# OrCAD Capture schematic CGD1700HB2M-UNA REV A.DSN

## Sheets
1 Power Supplies: size A; title: Power Supplies; rev: V1; note: CGD1700HB2M-UNA
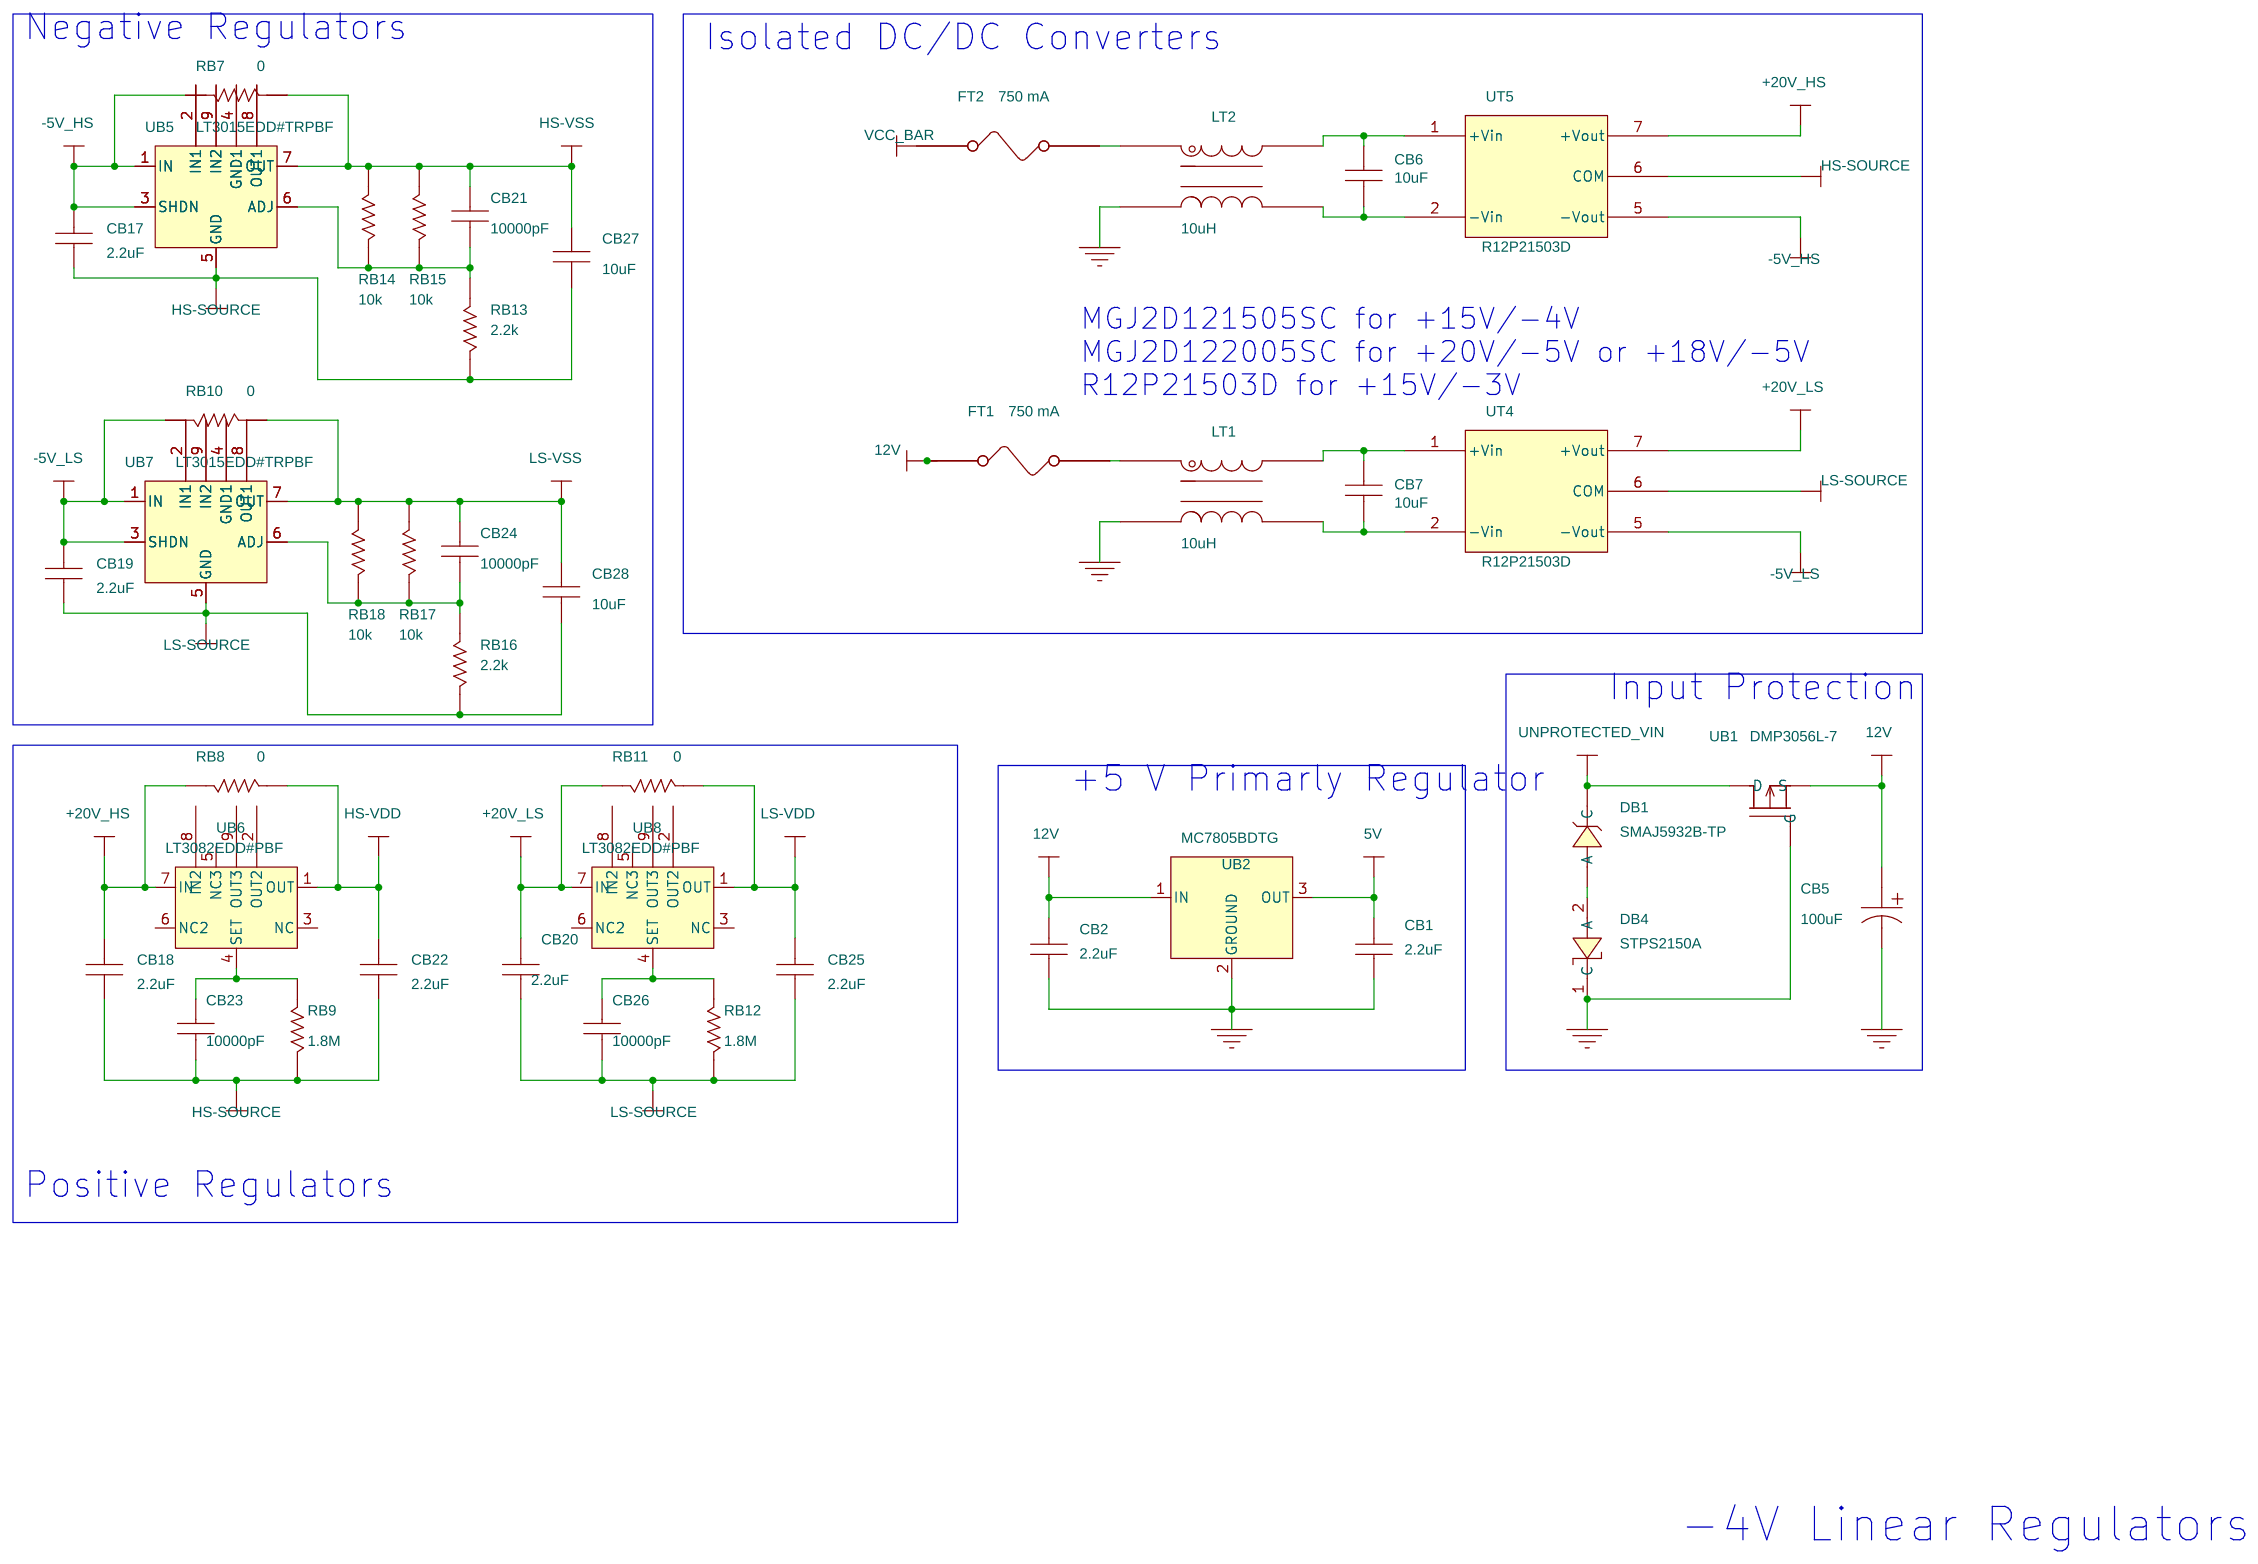
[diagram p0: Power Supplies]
2 Gate Driver: size B; title: Gate Drivers
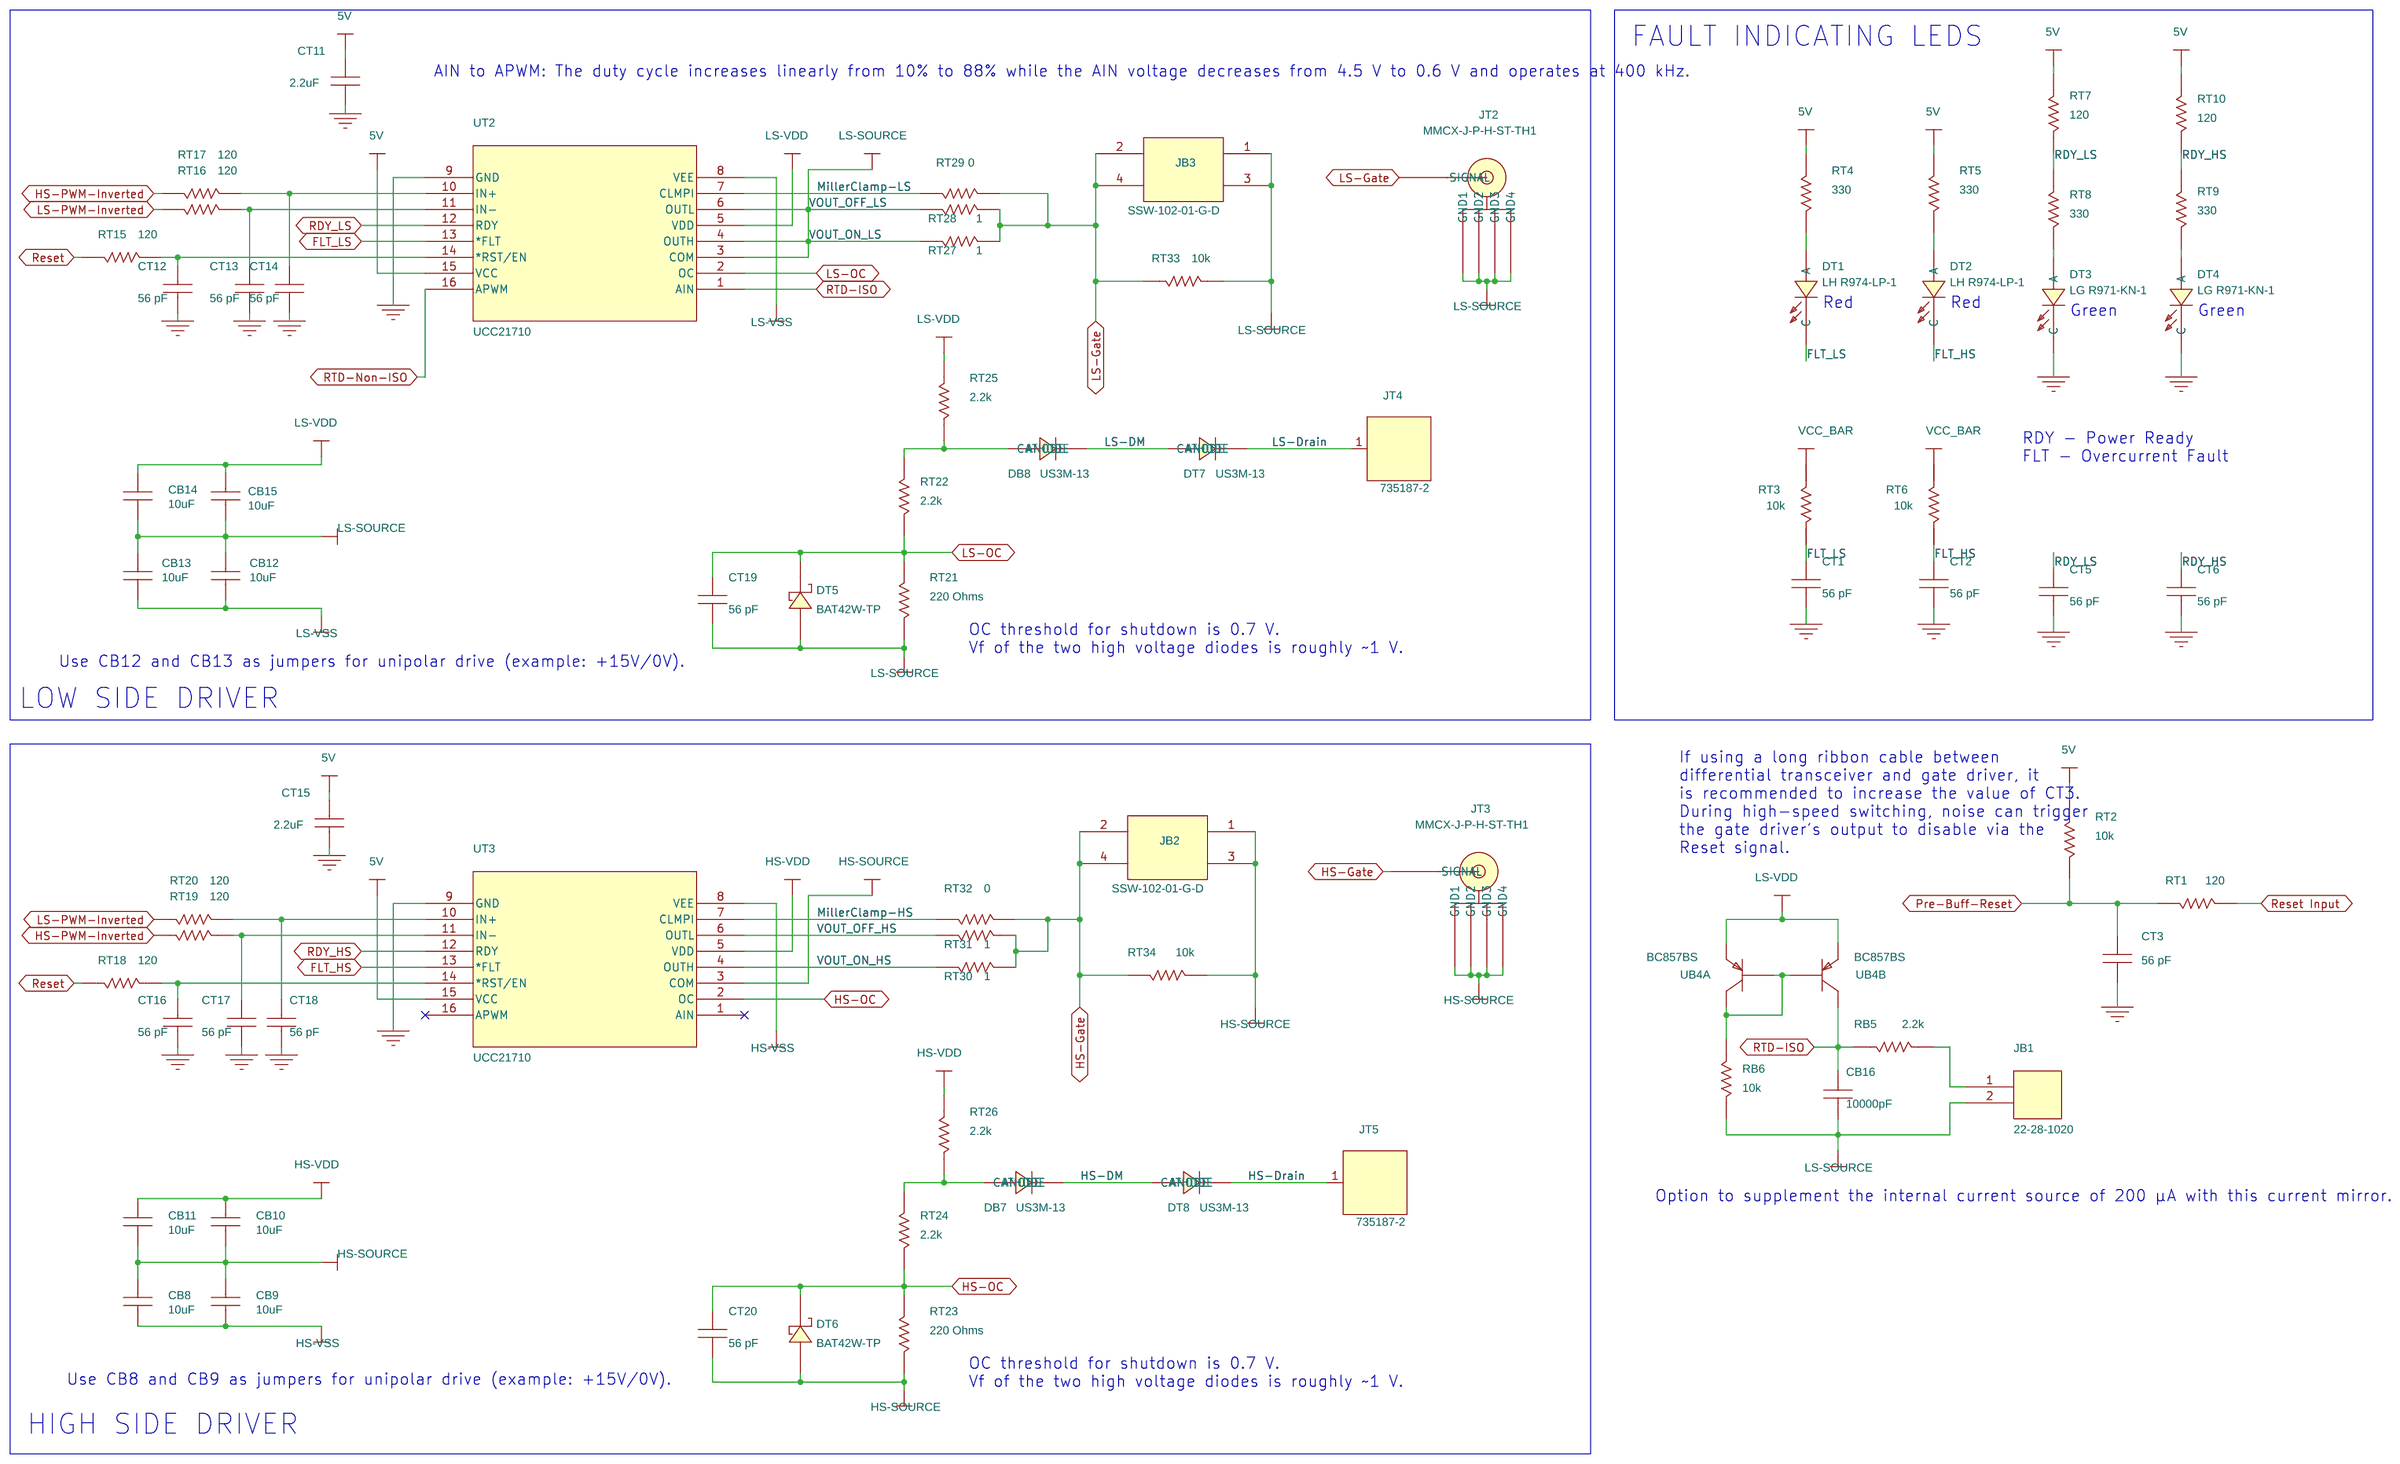
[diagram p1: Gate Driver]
3 Differential Signaling: size B; title: I/O and Conditioning
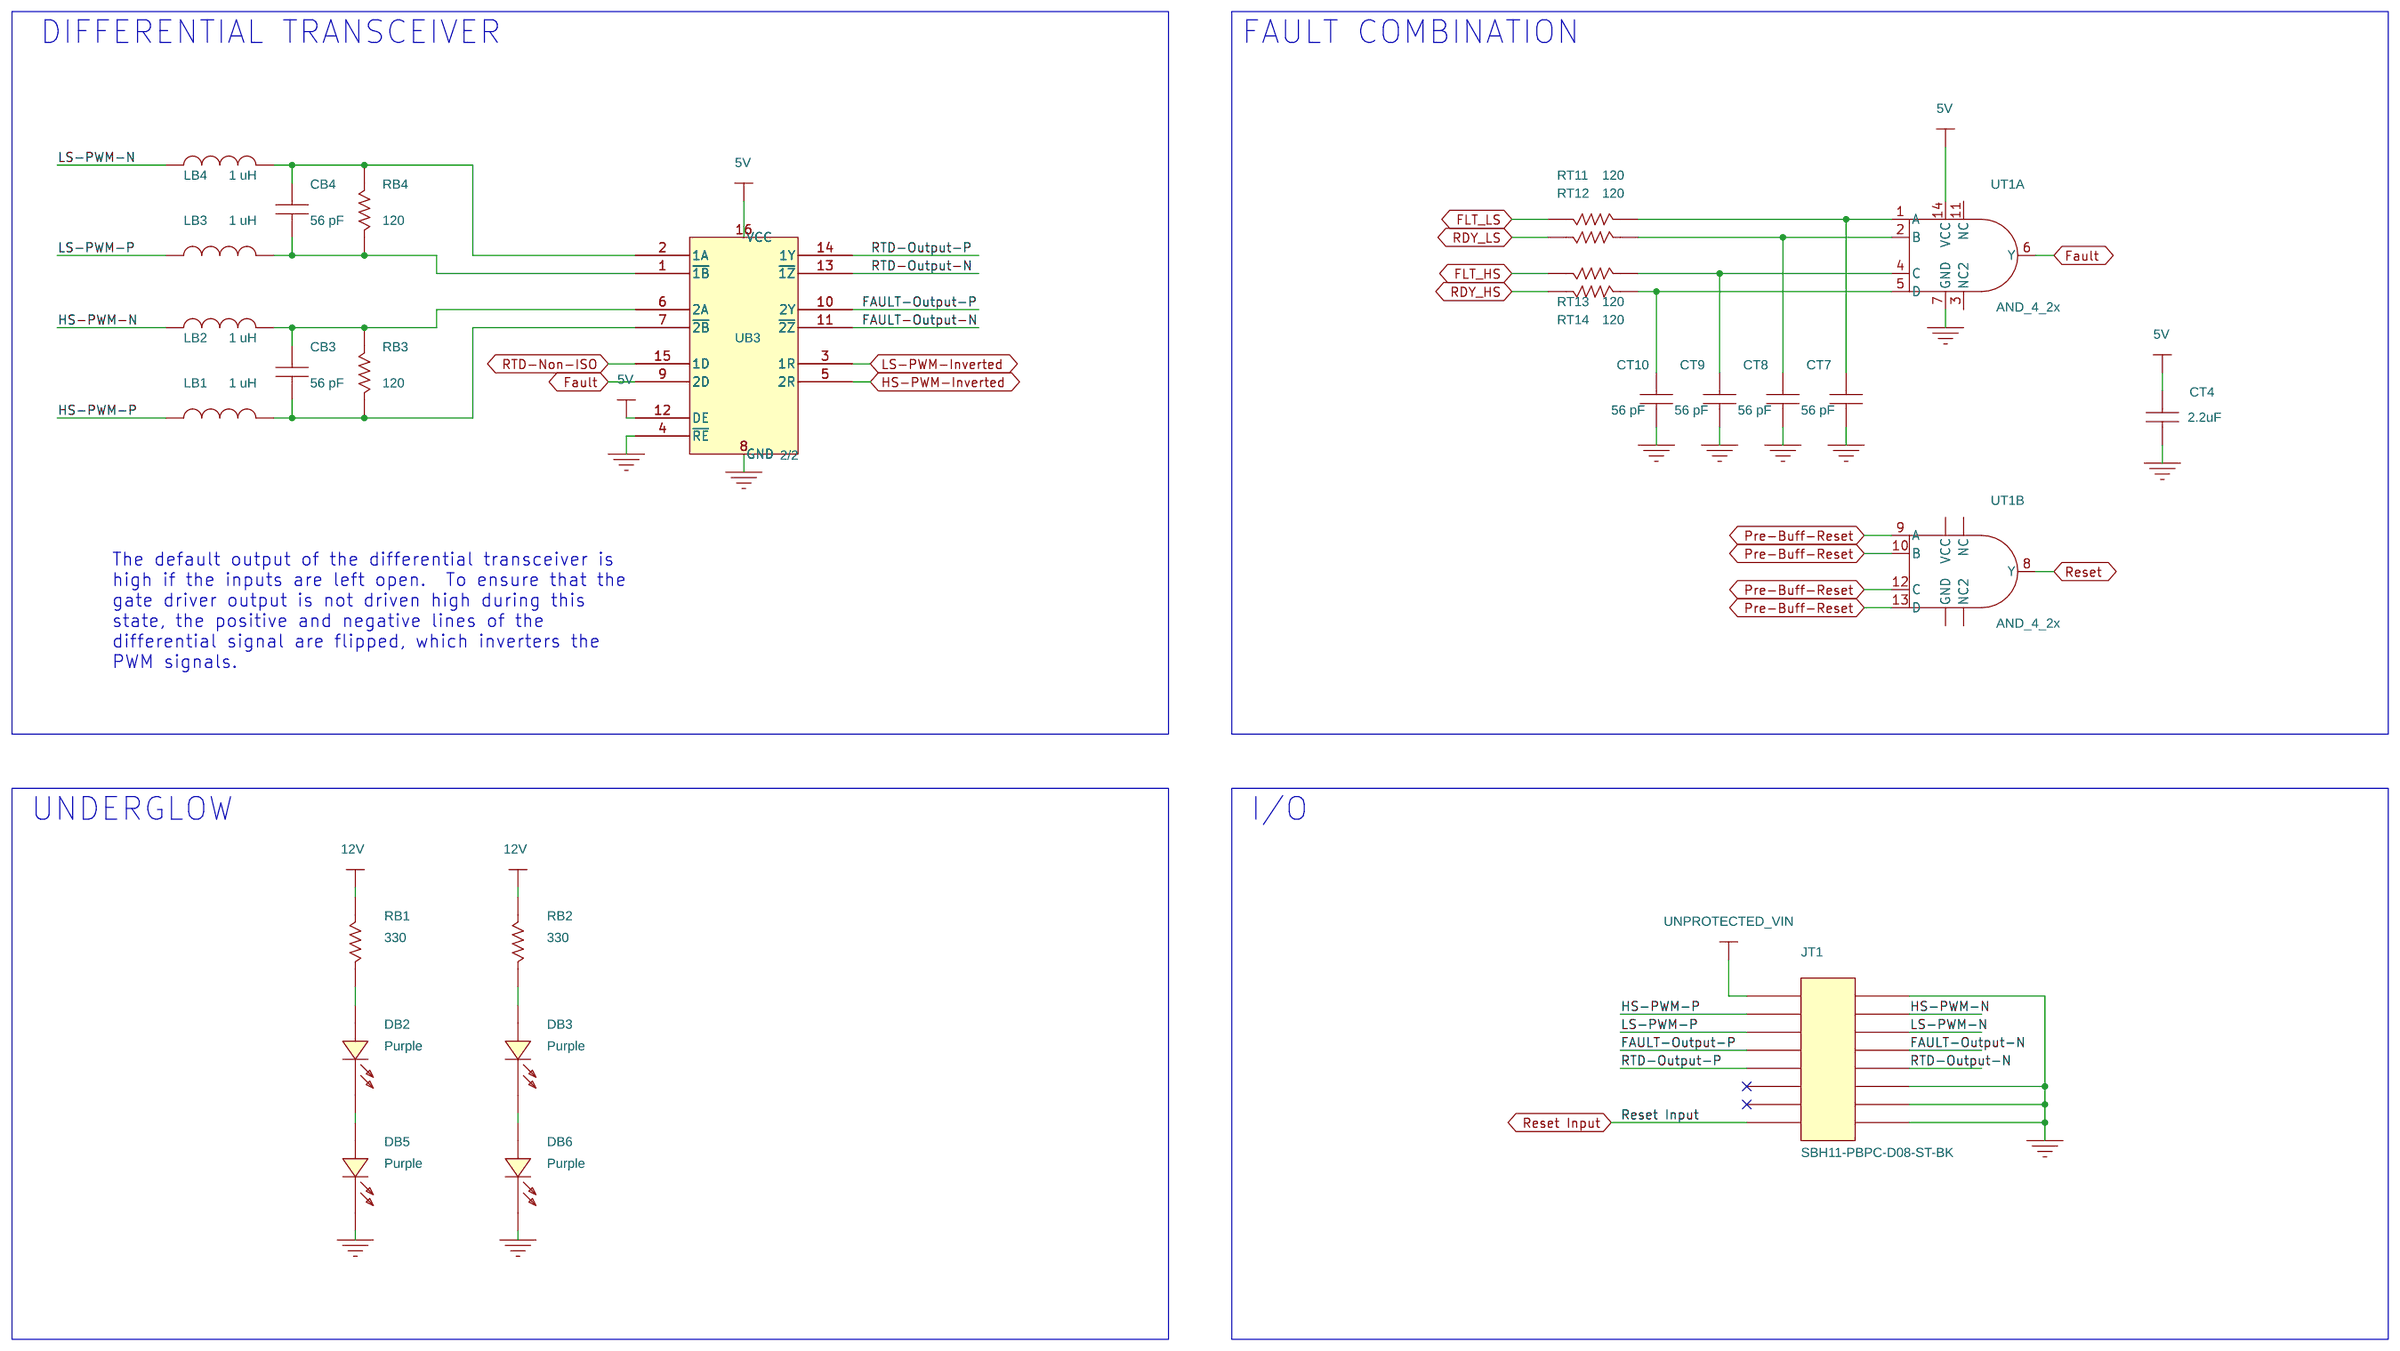
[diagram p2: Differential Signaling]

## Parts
sheet Differential Signaling
CB3  56 pF  [CAPC1608X90N]
CB4  56 pF  [CAPC1608X90N]
CT4  2.2uF  [CAPC1608X90N]
CT7  56 pF  [CAPC1608X90N]
CT8  56 pF  [CAPC1608X90N]
CT9  56 pF  [CAPC1608X90N]
CT10  56 pF  [CAPC1608X90N]
DB2  Purple  [D_1206]
DB3  Purple  [D_1206]
DB5  Purple  [D_1206]
DB6  Purple  [D_1206]
JT1  SBH11-PBPC-D08-ST-BK  [CON_2x8_shrouded_corrected]
LB1  1 uH  [INDC1608X95N]
LB2  1 uH  [INDC1608X95N]
LB3  1 uH  [INDC1608X95N]
LB4  1 uH  [INDC1608X95N]
RB1  330  [RESC1608X55N]
RB2  330  [RESC1608X55N]
RB3  120  [RESC1608X55N]
RB4  120  [RESC1608X55N]
RT11  120  [RESC1608X55N]
RT12  120  [RESC1608X55N]
RT13  120  [RESC1608X55N]
RT14  120  [RESC1608X55N]
UB3  2/2  [TSSOP_16]
UT1  AND_4_2x  [D14]  (sections A,B)
sheet Gate Driver
CB8  10uF  [C_1206]
CB9  10uF  [C_1206]
CB10  10uF  [C_1206]
CB11  10uF  [C_1206]
CB12  10uF  [C_1206]
CB13  10uF  [C_1206]
CB14  10uF  [C_1206]
CB15  10uF  [C_1206]
CB16  10000pF  [CAPC1608X90N]
CT1  56 pF  [CAPC1608X90N]
CT2  56 pF  [CAPC1608X90N]
CT3  56 pF  [CAPC1608X90N]
CT5  56 pF  [CAPC1608X90N]
CT6  56 pF  [CAPC1608X90N]
CT11  2.2uF  [CAPC1608X90N]
CT12  56 pF  [CAPC1608X90N]
CT13  56 pF  [CAPC1608X90N]
CT14  56 pF  [CAPC1608X90N]
CT15  2.2uF  [CAPC1608X90N]
CT16  56 pF  [CAPC1608X90N]
CT17  56 pF  [CAPC1608X90N]
CT18  56 pF  [CAPC1608X90N]
CT19  56 pF  [CAPC1608X90N]
CT20  56 pF  [CAPC1608X90N]
DB7  US3M-13  [DO-214AB-SMC]
DB8  US3M-13  [DO-214AB-SMC]
DT1  LH R974-LP-1  [D_0805]
DT2  LH R974-LP-1  [D_0805]
DT3  LG R971-KN-1  [D_0805]
DT4  LG R971-KN-1  [D_0805]
DT5  BAT42W-TP  [SOD123]
DT6  BAT42W-TP  [SOD123]
DT7  US3M-13  [DO-214AB-SMC]
DT8  US3M-13  [DO-214AB-SMC]
JB1  22-28-1020  [CONN_HEADER_RA_2POS_LOCKING]
JB2  SSW-102-01-G-D  [CON_2x2_100mil_TH]
JB3  SSW-102-01-G-D  [CON_2x2_100mil_TH]
JT2  MMCX-J-P-H-ST-TH1  [MMCX_PLUG_TH]
JT3  MMCX-J-P-H-ST-TH1  [MMCX_PLUG_TH]
JT4  735187-2  [con_1x1_63mil]
JT5  735187-2  [con_1x1_63mil]
RB5  2.2k  [RESC1608X55N]
RB6  10k  [RESC1608X55N]
RT1  120  [RESC1608X55N]
RT2  10k  [RESC1608X55N]
RT3  10k  [RESC1608X55N]
RT4  330  [RESC1608X55N]
RT5  330  [RESC1608X55N]
RT6  10k  [RESC1608X55N]
RT7  120  [RESC1608X55N]
RT8  330  [RESC1608X55N]
RT9  330  [RESC1608X55N]
RT10  120  [RESC1608X55N]
RT15  120  [RESC1608X55N]
RT16  120  [RESC1608X55N]
RT17  120  [RESC1608X55N]
RT18  120  [RESC1608X55N]
RT19  120  [RESC1608X55N]
RT20  120  [RESC1608X55N]
RT21  220 Ohms  [RESC1608X55N]
RT22  2.2k  [RESC1608X55N]
RT23  220 Ohms  [RESC1608X55N]
RT24  2.2k  [RESC1608X55N]
RT25  2.2k  [RESC1608X55N]
RT26  2.2k  [RESC1608X55N]
RT27  1  [RESC6432X70N]
RT28  1  [RESC6432X70N]
RT29  0  [RESC3216X70N]
RT30  1  [RESC6432X70N]
RT31  1  [RESC6432X70N]
RT32  0  [RESC3216X70N]
RT33  10k  [RESC1608X55N]
RT34  10k  [RESC1608X55N]
UB4  BC857BS  [SOT363_NEX]  (sections A,B)
UT2  UCC21710  [DW16_TEX]
UT3  UCC21710  [DW16_TEX]
sheet Power Supplies
CB1  2.2uF  [CAPC1608X90N]
CB2  2.2uF  [CAPC1608X90N]
CB5  100uF  [CAPMP7343X430N]
CB6  10uF  [C_1206]
CB7  10uF  [C_1206]
CB17  2.2uF  [CAPC1608X90N]
CB18  2.2uF  [CAPC1608X90N]
CB19  2.2uF  [CAPC1608X90N]
CB20  2.2uF  [CAPC1608X90N]
CB21  10000pF  [CAPC1608X90N]
CB22  2.2uF  [CAPC1608X90N]
CB23  10000pF  [CAPC1608X90N]
CB24  10000pF  [CAPC1608X90N]
CB25  2.2uF  [CAPC1608X90N]
CB26  10000pF  [CAPC1608X90N]
CB27  10uF  [C_1206]
CB28  10uF  [C_1206]
DB1  SMAJ5932B-TP  [do-214ac]
DB4  STPS2150A  [do-214ac]
FT1  750 mA  [FUSE_SMD_SSQ2410]
FT2  750 mA  [FUSE_SMD_SSQ2410]
LT1  10uH  [SRF0905]
LT2  10uH  [SRF0905]
RB7  0  [RESC3216X70N]
RB8  0  [RESC3216X70N]
RB9  1.8M  [RESC3216X70N]
RB10  0  [RESC3216X70N]
RB11  0  [RESC3216X70N]
RB12  1.8M  [RESC3216X70N]
RB13  2.2k  [RESC1608X55N]
RB14  10k  [RESC1608X55N]
RB15  10k  [RESC1608X55N]
RB16  2.2k  [RESC1608X55N]
RB17  10k  [RESC1608X55N]
RB18  10k  [RESC1608X55N]
UB1  DMP3056L-7  [SOT_23_3]
UB2  MC7805BDTG  [DPAK-3]
UB5  LT3015EDD#TRPBF  [8-WDFN_Exposed_Pad]
UB6  LT3082EDD#PBF  [8-WDFN_Exposed_Pad]
UB7  LT3015EDD#TRPBF  [8-WDFN_Exposed_Pad]
UB8  LT3082EDD#PBF  [8-WDFN_Exposed_Pad]
UT4  R12P21503D  [MGJ2]
UT5  R12P21503D  [MGJ2]

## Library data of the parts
CB3 CB4 CT1-CT3 CT5-CT10 CT12-CT14 CT16-CT20 = CAP: CAP CER 56PF 50V C0G/NP0 0603; CLASS: DISCRETE; Dielectric Type: Capacitors; Manufacturer: Samsung Electro-Mechanics; Manufacturer PN: CL10C560JB8NNNC; PART_NUMBER: TMP-1515; Package Size: 0603 (1608 Metric); Temperature Coefficient: C0G, NP0; Tolerance: 5%
CB1 CB2 CB17-CB20 CB22 CB25 CT4 CT11 CT15 = CAP: CAP CER 2.2UF 50V X5R 0603; CLASS: DISCRETE; Company Part Status: Obsolete; Manufacturer: Murata Electronics North America; Manufacturer PN: GRT188R61H225ME13D; PART_NUMBER: TMP-1549; Package Size: 0603 (1608 Metric); Rated Voltage: 50V; Temperature Coefficient: X5R; Tolerance: 20%
DB2 DB3 DB5 DB6 = LED_-_Purple: Standard LEDs - SMD 3.2x1.6mm PURPLE; CLASS: DISCRETE; Company Part Status: New; Manufacturer PN: APTR3216-VFX; PART_NUMBER: TMP-1694; Package Size: 1206 (3216 metric)
JT1 = CON16A_Corrected: CONN HEADER 2.54MM 16POS GOLD; CLASS: IO; Manufacturer: Sullins Connector Solutions; PART_NUMBER: TMP-739
LB1-LB4 = INDUCTOR: FIXED IND 1UH 600MA 150 MOHM SMD; CLASS: DISCRETE; Manufacturer: TDK Corporation; Manufacturer PN: MLZ1608A1R0WT000; PART_NUMBER: TMP-1514; Package Size: 0603 (1608 Metric); Tolerance: 20%
RB1 RB2 RT4 RT5 RT8 RT9 = RES: RES SMD 330 OHM 5% 1/10W 0603; CLASS: DISCRETE; Company Part Status: Released; Manufacturer: Yageo; Manufacturer PN: RC0603JR-07330RL; PART_NUMBER: TMP-1554; Package Size: 0603 (1608 Metric); Rated Power: 0.1W, 1/10W; Temperature Coefficient: 100ppm/C; Tolerance: 5%
RB3 RB4 RT1 RT11-RT14 = RES: RES SMD 120 OHM 1% 1/10W 0603; CLASS: DISCRETE; Manufacturer: Yageo; Manufacturer PN: RC0603FR-07120RL; PART_NUMBER: TMP-957; Package Size: 0603 (1608 Metric); Rated Power: 0.1W, 1/10W; Temperature Coefficient: 100ppm/C; Tolerance: 1%
UB3 = SN65C1167: IC DIFF DVR/RCVR DUAL 16-TSSOP; CLASS: IC; Company Part Status: Released; Manufacturer: Texas Instruments; Manufacturer PN: SN65C1167EPWR; PART_NUMBER: TMP-1588; Package Size: 16-TSSOP (0.173", 4.40mm Width); Supply Voltage: 4.5V ~ 5.5V
UT1 = AND4_2X: IC GATE AND 2CH 4-INP 14SOIC; CLASS: IC; Company Part Status: Released; Manufacturer: Texas Instruments; Manufacturer PN: SN74HC21DR; PART_NUMBER: TMP-1541; Package Size: 14-SOIC (0.154", 3.90mm Width); Supply Voltage: 2 V - 6 V
CB6-CB15 CB27 CB28 = CAP: CAP CER 10UF 16V X7R 1206; CLASS: DISCRETE; Company Part Status: New; Dielectric Type: Capacitors; Manufacturer: Murata Electronics North America; Manufacturer PN: GCM31CR71C106KA64L; PART_NUMBER: TMP-885; Package Size: 1206 (3216 Metric); Rated Voltage: 16V; Temperature Coefficient: X7R; Tolerance: 10%
CB16 CB21 CB23 CB24 CB26 = CAP: CAP CER 10000PF 25V 10% X7R 0603; CLASS: DISCRETE; Company Part Status: New; Dielectric Type: Capacitors; Manufacturer: Samsung Electro-Mechanics America, Inc.; Manufacturer PN: CL10B103KA8NNNC; PART_NUMBER: TMP-566; Package Size: 0603 (1608 Metric); Rated Voltage: 25V; Temperature Coefficient: X7R; Tolerance: 10%
DB7 DB8 DT7 DT8 = DIODE_1: DIODE GEN PURP 1KV 3A SMC; CLASS: DISCRETE; Manufacturer: Diodes Incorporated; PART_NUMBER: TMP-1412; Package Size: DO-214AB, SMC
DT1 DT2 = LED: LED RED DIFFUSED 0805 SMD; CLASS: DISCRETE; Manufacturer: OSRAM Opto Semiconductors Inc.; PART_NUMBER: TMP-917; Package Size: 0805 (2012 Metric); Rated Voltage: 1.8V @ 20mA
DT3 DT4 = LED: LED GREEN DIFFUSED 0805 SMD; CLASS: DISCRETE; Manufacturer: OSRAM Opto Semiconductors Inc.; PART_NUMBER: TMP-915; Package Size: 0805 (2012 Metric); Rated Voltage: 2.2V
DT5 DT6 = DIODE_SCHOTTKY_11: DIODE SCHOTTKY 30V 200MA SOD123; CLASS: DISCRETE; Company Part Status: Released; Manufacturer: Micro Commercial Co; PART_NUMBER: TMP-1535; Package Size: SOD-123; Rated Voltage: 30 V
JB1 = CON2: CONN HEADER R/A 2POS 2.54MM; CLASS: IO; Company Part Status: Released; Manufacturer: Molex; Manufacturer PN: 0022281020; PART_NUMBER: TMP-1695
JB2 JB3 = CON_2x2_100mil: CONN RCPT 4POS 0.1 GOLD PCB; CLASS: IO; Company Part Status: Released; Manufacturer: Samtec Inc.; PART_NUMBER: TMP-1689
JT2 JT3 = BNC_5P: CONN MMCX JACK STR 50 OHM PCB; CLASS: IO; Company Part Status: Released; Contact Voltage: 500V; Manufacturer: Samtec Inc.; PART_NUMBER: TMP-1696
JT4 JT5 = HDR_1X1_M: CONN QC TAB 0.110 SOLDER; CLASS: IO; Manufacturer: TE Connectivity AMP Connectors; PART_NUMBER: TMP-635
RB5 RB13 RB16 RT22 RT24-RT26 = RES: RES SMD 2.2K OHM 1% 1/10W 0603; CLASS: DISCRETE; Company Part Status: New; Manufacturer: Yageo; Manufacturer PN: RC0603FR-072K2L; PART_NUMBER: TMP-1308; Package Size: 0603 (1608 Metric); Rated Power: 0.1W, 1/10W; Temperature Coefficient: 100ppm/C; Tolerance: 1%
RB6 RB14 RB15 RB17 RB18 RT2 RT3 RT6 RT33 RT34 = RES: RES SMD 10K OHM 1% 1/10W 0603; CLASS: DISCRETE; Company Part Status: New; Manufacturer: Panasonic Electronic Components; Manufacturer PN: ERJ-3EKF1002V; PART_NUMBER: TMP-788; Package Size: 0603 (1608 Metric); Rated Power: 0.1W, 1/10W; Temperature Coefficient: 100ppm/C; Tolerance: 1%
RT7 RT10 RT15-RT20 = RES: RES SMD 120 OHM 1% 1/10W 0603; CLASS: DISCRETE; Company Part Status: Released; Manufacturer: Yageo; Manufacturer PN: RC0603FR-07120RL; PART_NUMBER: TMP-957; Package Size: 0603 (1608 Metric); Rated Power: 0.1W, 1/10W; Temperature Coefficient: 100ppm/C; Tolerance: 1%
RT21 RT23 = RES: RES SMD 220 OHM 1% 1/10W 0603; CLASS: DISCRETE; Company Part Status: Released; Manufacturer: Yageo; Manufacturer PN: RC0603FR-07220RL; PART_NUMBER: TMP-1742; Package Size: 0603 (1608 Metric); Rated Power: 0.1W, 1/10W; Temperature Coefficient: 100ppm/C; Tolerance: 1%
RT27 RT28 RT30 RT31 = RES: RES SMD 1 OHM 1% 1.5W 2512; CLASS: DISCRETE; Company Part Status: Released; Manufacturer: Vishay Dale; Manufacturer PN: CRCW25121R00FKEGHP; PART_NUMBER: TMP-1587; Package Size: 2512 (6432 Metric); Rated Power: 1.5W; Temperature Coefficient: 100ppm/C; Tolerance: 1%
RB7 RB8 RB10 RB11 RT29 RT32 = RES: RES SMD 0 OHM JUMPER 1/4W 1206; CLASS: DISCRETE; Company Part Status: Released; Manufacturer: Panasonic Electronic Components; Manufacturer PN: ERJ-8GEY0R00V; PART_NUMBER: TMP-1692; Package Size: 1206 (3216 Metric); Rated Power: 0.25W, 1/4W; Tolerance: Jumper
UB4 = DUAL_PNP: TRANS 2PNP 45V 0.1A 6TSSOP; CLASS: DISCRETE; Company Part Status: Released; Manufacturer: Nexperia USA Inc.; Manufacturer PN: BC857BS,115; PART_NUMBER: TMP-1677; Package Size: 6-TSSOP, SC-88, SOT-363; Polarity: 2 PNP (Dual); Rated Power: 200mW
UT2 UT3 = UCC21710QDWRQ1: 10A Gate Driver Capacitive Coupling 5700Vrms 1 Channel 16-SOIC; CLASS: IC; Company Part Status: Released; Manufacturer: Texas Instruments; PART_NUMBER: TMP-1688; Package Size: 16-SOIC (0.295", 7.50mm Width)
CB5 = CAP_P: CAP TANT 100UF 10% 25V 2917; CLASS: DISCRETE; Company Part Status: Released; Manufacturer: KEMET; Manufacturer PN: T491X107K025AT; PART_NUMBER: TMP-1697; Package Size: 2917 (7343 Metric); Rated Voltage: 25V; Tolerance: 10%
DB1 = DIODE_ZENER: DIODE ZENER 20V 1.5W DO214AC; CLASS: DISCRETE; Company Part Status: New; Manufacturer: Micro Commercial Co; PART_NUMBER: TMP-1179; Package Size: DO-214AC, SMA; Rated Power: 1.5W; Rated Voltage: 20V
DB4 = DIODE_SCHOTTKY_12: DIODE SCHOTTKY 150V 2A SMA; CLASS: DISCRETE; Company Part Status: New; Manufacturer: STMicroelectronics; PART_NUMBER: TMP-523; Package Size: DO-214AC, SMA; Rated Voltage: 820mV @ 2A
FT1 FT2 = FUSE: FUSE BOARD MNT 750MA 125VAC/VDC; CLASS: DISCRETE; Manufacturer: Bel Fuse Inc.; Manufacturer PN: SSQ 750; PART_NUMBER: TMP-1389; Package Size: 0.240" L x 0.100" W x 0.100" H (6.10mm x 2.54mm x 2.54mm)
LT1 LT2 = CM_choke_-_LPD3015_2: INDUCTOR COMMON MODE 10UH 1.6A; CLASS: DISCRETE; Manufacturer: Bourns Inc.; Manufacturer PN: SRF0905-100Y; PART_NUMBER: TMP-846; Package Size: Horizontal, 4 PC Pad
RB9 RB12 = RES: RES SMD 1.8M OHM 1% 1/4W 1206; CLASS: DISCRETE; Company Part Status: Released; Manufacturer: Panasonic Electronic Components; Manufacturer PN: ERJ-8ENF1804V; PART_NUMBER: TMP-1691; Package Size: 1206 (3216 Metric); Rated Power: 0.25W, 1/4W; Temperature Coefficient: 100ppm/C; Tolerance: 1%
UB1 = MOSFET_P_GSD: MOSFET P-CH 30V 4.3A SOT23; CLASS: DISCRETE; Manufacturer: Diodes Incorporated; PART_NUMBER: TMP-1395; Package Size: TO-236-3, SC-59, SOT-23-3; Polarity: P-Channel
UB2 = MC7805BDTG: IC REG LINEAR 5V 1A DPAK; CLASS: IC; Company Part Status: Released; Manufacturer: ON Semiconductor; PART_NUMBER: TMP-1562; Package Size: TO-252-3, DPak (2 Leads + Tab), SC-63
UB5 UB7 = LT3015: IC REG LINEAR NEG ADJ 1.5A 8DFN; CLASS: IC; Manufacturer: Linear Technology/Analog Devices; PART_NUMBER: TMP-1383; Package Size: 8-WFDFN Exposed Pad
UB6 UB8 = LT3082_0: IC REG LIN POS ADJ 200MA 8DFN; CLASS: IC; Manufacturer: Linear Technology; PART_NUMBER: TMP-1300; Package Size: 8-WFDFN Exposed Pad
UT4 UT5 = MGJ2: DC DC CONVERTER 15V -3V; CLASS: IC; Company Part Status: Released; Manufacturer: Recom Power; Manufacturer PN: R15P21503D; PART_NUMBER: TMP-1693; Package Size: 7-SIP Module, 5 Leads; Rated Power: 2W

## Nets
5V: CB1.2 CT4.1 CT11.1 CT15.1 RT2.1 RT3.1 RT4.2 RT5.2 RT6.1 RT7.2 RT10.2 UB2.3(OUT) UB3.12(DE) UB3.16(VCC) UT1.14(VCC) UT2.15(VCC) UT3.15(VCC)
12V: CB2.2 CB5.1 FT1.1 FT2.1 RB1.2 RB2.2 UB1.2(S) UB2.1(IN)
+20V_HS: CB18.2 RB8.1 UB6.7(IN) UT5.7(+Vout)
+20V_LS: CB20.2 RB11.1 UB8.7(IN) UT4.7(+Vout)
-5V_HS: CB17.2 RB7.1 UB5.1(IN) UB5.3(SHDN) UT5.5(-Vout)
-5V_LS: CB19.2 RB10.1 UB7.1(IN) UB7.3(SHDN) UT4.5(-Vout)
0: CB1.1 CB2.1 CB5.2 CT1.2 CT2.2 CT3.2 CT4.2 CT5.2 CT6.2 CT7.2 CT8.2 CT9.2 CT10.2 CT11.2 CT12.2 CT13.2 CT14.2 CT15.2 CT16.2 CT17.2 CT18.2 DB4.1(C) DB5.2(CATHODE) DB6.2(CATHODE) DT3.2(C) DT4.2(C) JT1.2 JT1.12 JT1.14 JT1.16 LT1.2 LT2.2 UB1.1(G) UB2.2(GROUND) UB3.4(~{RE}) UB3.8(GND) UT1.7(GND) UT2.9(GND) UT3.9(GND)
Fault: UB3.9(2D) UT1.6(Y)
FAULT-Output-N: JT1.8 UB3.11(~{2Z})
FAULT-Output-P: JT1.7 UB3.10(2Y)
FLT_HS: CT2.1 DT2.2(C) RT6.2 RT13.1 UT3.13(*FLT)
FLT_LS: CT1.1 DT1.2(C) RT3.2 RT11.1 UT2.13(*FLT)
HS-DM: DB7.C(CATHODE) DT8.A(ANODE)
HS-Drain: DT8.C(CATHODE) JT5.1
HS-Gate: JB2.2 JB2.4 JT3.1(SIGNAL) RT30.2 RT31.2 RT32.2 RT34.1
HS-OC: CT20.1 DT6.C RT23.2 RT24.1 UT3.2(OC)
HS-PWM-Inverted: RT17.1 RT19.1 UB3.5(2R)
HS-PWM-N: JT1.4 LB2.1
HS-PWM-P: JT1.3 LB1.1
HS-Source: CB8.1 CB9.1 CB10.2 CB11.2 CB17.1 CB18.1 CB22.1 CB23.2 CB27.2 CT20.2 DT6.A JB2.1 JB2.3 JT3.2(GND1) JT3.3(GND2) JT3.4(GND3) JT3.5(GND4) RB9.2 RB13.1 RT23.1 RT34.2 UB5.5(GND) UT3.3(COM) UT5.6(COM)
HS-VDD: CB10.1 CB11.1 CB22.2 RB8.2 RT26.2 UB6.1(OUT) UT3.5(VDD)
HS-VSS: CB8.2 CB9.2 CB21.1 CB27.1 RB7.2 RB14.1 RB15.1 UB5.7(OUT) UT3.8(VEE)
LS-DM: DB8.C(CATHODE) DT7.A(ANODE)
LS-Drain: DT7.C(CATHODE) JT4.1
LS-Gate: JB3.2 JB3.4 JT2.1(SIGNAL) RT27.2 RT28.2 RT29.2 RT33.1
LS-OC: CT19.1 DT5.C RT21.2 RT22.1 UT2.2(OC)
LS-PWM-Inverted: RT16.1 RT20.1 UB3.3(1R)
LS-PWM-N: JT1.6 LB4.1
LS-PWM-P: JT1.5 LB3.1
LS-Source: CB12.1 CB13.1 CB14.2 CB15.2 CB16.2 CB19.1 CB20.1 CB25.1 CB26.2 CB28.2 CT19.2 DT5.A JB1.2 JB3.1 JB3.3 JT2.2(GND1) JT2.3(GND2) JT2.4(GND3) JT2.5(GND4) RB6.1 RB12.2 RB16.1 RT21.1 RT33.2 UB7.5(GND) UT2.3(COM) UT4.6(COM)
LS-VDD: CB14.1 CB15.1 CB25.2 RB11.2 RT25.2 UB4.1(Emitter) UB4.4(Emitter) UB8.1(OUT) UT2.5(VDD)
LS-VSS: CB12.2 CB13.2 CB24.1 CB28.1 RB10.2 RB17.1 RB18.1 UB7.7(OUT) UT2.8(VEE)
MillerClamp-HS: RT32.1 UT3.7(CLMPI)
MillerClamp-LS: RT29.1 UT2.7(CLMPI)
NC: UT1.11(NC)
NC2: UT1.3(NC2)
Pre-Buff-Reset: CT3.1 RT1.1 RT2.2 UT1.9(A) UT1.10(B) UT1.12(C) UT1.13(D)
RDY_HS: CT6.1 RT9.2 RT10.1 RT14.1 UT3.12(RDY)
RDY_LS: CT5.1 RT7.1 RT8.2 RT12.1 UT2.12(RDY)
Reset: RT15.1 RT18.1 UT1.8(Y)
Reset Input: JT1.15 RT1.2
RTD-ISO: CB16.1 RB5.1 UB4.3(Collector) UT2.1(AIN)
RTD-Non-ISO: UB3.15(1D) UT2.16(APWM)
RTD-Output-N: JT1.10 UB3.13(~{1Z})
RTD-Output-P: JT1.9 UB3.14(1Y)
Unprotected_VIN: DB1.1(C) JT1.1 UB1.3(D)
VOUT_OFF_HS: RT31.1 UT3.6(OUTL)
VOUT_OFF_LS: RT28.1 UT2.6(OUTL)
VOUT_ON_HS: RT30.1 UT3.4(OUTH)
VOUT_ON_LS: RT27.1 UT2.4(OUTH)
N5110410: CT14.1 RT17.2 UT2.10(IN+)
N5777665: CB6.1 LT2.4 UT5.1(+Vin)
N5777737: CB6.2 LT2.3 UT5.2(-Vin)
N5778706: CB7.1 LT1.4 UT4.1(+Vin)
N5778794: CB7.2 LT1.3 UT4.2(-Vin)
N5780153: FT1.2 LT1.1
N5786131: CB4.1 LB4.2 RB4.2 UB3.2(1A)
N5786223: CB4.2 LB3.2 RB4.1 UB3.1(~{1B})
N5786329: CB3.1 LB2.2 RB3.2 UB3.6(2A)
N5786365: CB3.2 LB1.2 RB3.1 UB3.7(~{2B})
N5791884: DT1.1(A) RT4.1
N5791888: DT2.1(A) RT5.1
N5813663: CT7.1 RT11.2 UT1.1(A)
N5871306: CT9.1 RT13.2 UT1.4(C)
N5927082: DB1.2(A) DB4.2(A)
N5941912: CT8.1 RT12.2 UT1.2(B)
N5941952: CT10.1 RT14.2 UT1.5(D)
N5948959: CB21.2 RB13.2 RB14.2 RB15.2 UB5.6(ADJ)
N5949233: CB24.2 RB16.2 RB17.2 RB18.2 UB7.6(ADJ)
N6007380: DT3.1(A) RT8.1
N6007384: DT4.1(A) RT9.1
N6009832: DB8.A(ANODE) RT22.2 RT25.1
N6026363: CT18.1 RT20.2 UT3.10(IN+)
N6026535: CT16.1 RT18.2 UT3.14(*RST/EN)
N6032095: CT12.1 RT15.2 UT2.14(*RST/EN)
N6067568: CB23.1 RB9.1 UB6.4(SET)
N6067584: CB26.1 RB12.1 UB8.4(SET)
N6072371: JB1.1 RB5.2
N6073188: CT13.1 RT16.2 UT2.11(IN-)
N6075364: DB7.A(ANODE) RT24.2 RT26.1
N6076004: CT17.1 RT19.2 UT3.11(IN-)
N6084683: RB6.2 UB4.2(Base) UB4.5(Base) UB4.6(Collector)
N6088850: DB2.2(CATHODE) DB5.1(ANODE)
N6089152: DB3.2(CATHODE) DB6.1(ANODE)
N6093449: FT2.2 LT2.1
N6093607: DB3.1(ANODE) RB2.1
N6093609: DB2.1(ANODE) RB1.1

Not connected (* = marked no-connect by the designer): JT1 11* 13*; UB5 2(IN1) 4(GND1) 8(OUT1) 9(IN2); UB6 2(OUT2) 3(NC) 5(NC3) 6(NC2) 8(IN2) 9(OUT3); UB7 2(IN1) 4(GND1) 8(OUT1) 9(IN2); UB8 2(OUT2) 3(NC) 5(NC3) 6(NC2) 8(IN2) 9(OUT3); UT1 GND NC NC2 VCC; UT3 1(AIN)* 16(APWM)*

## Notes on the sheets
sheet 1
- Negative Regulators
- Isolated DC/DC Converters
- MGJ2D121505SC for +15V/-4V
  MGJ2D122005SC for +20V/-5V or +18V/-5V
  R12P21503D for +15V/-3V
- Input Protection
- +5 V Primarly Regulator
- Positive Regulators
- -4V Linear Regulators
sheet 2
- FAULT INDICATING LEDS
- AIN to APWM: The duty cycle increases linearly from 10% to 88% while the AIN voltage decreases from 4.5 V to 0.6 V and operates at 400 kHz.
- Red
- Red
- Green
- Green
- RDY - Power Ready
  FLT - Overcurrent Fault
- OC threshold for shutdown is 0.7 V.
  Vf of the two high voltage diodes is roughly ~1 V.
- Use CB12 and CB13 as jumpers for unipolar drive (example: +15V/0V).
- LOW SIDE DRIVER
- If using a long ribbon cable between
  differential transceiver and gate driver, it
  is recommended to increase the value of CT3.
  During high-speed switching, noise can trigger
  the gate driver's output to disable via the
  Reset signal.
- Option to supplement the internal current source of 200 µA with this current mirror.
- Use CB8 and CB9 as jumpers for unipolar drive (example: +15V/0V).
- OC threshold for shutdown is 0.7 V.
  Vf of the two high voltage diodes is roughly ~1 V.
- HIGH SIDE DRIVER
sheet 3
- DIFFERENTIAL TRANSCEIVER
- FAULT COMBINATION
- The default output of the differential transceiver is
  high if the inputs are left open.  To ensure that the
  gate driver output is not driven high during this
  state, the positive and negative lines of the
  differential signal are flipped, which inverters the
  PWM signals.
- UNDERGLOW
- I/O
